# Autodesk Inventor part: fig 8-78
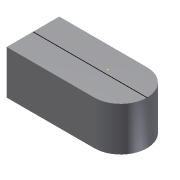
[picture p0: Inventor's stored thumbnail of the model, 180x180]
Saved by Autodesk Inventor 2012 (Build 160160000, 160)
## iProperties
Created: 2011-07
Part Number: fig 8-78
Material: Default
Document SubType Name: Modeling
Designer: CadCim
Density: 1 g/cm^3
Author: CadCim
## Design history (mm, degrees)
sketch "Sketch1"
  geometry: L1 (-16, 5)-(-16, -7); L2 (-16, -7)-(4, -7); L3 (4, 5)-(-16, 5); A1 r 6 centre (4, -1) between (4, -7) and (4, 5); 1 further point
  constraints: 6 end point, 2 point on circle, 2 tangent, 1 centre point, 1 parallel, 1 perpendicular, 1 vertical
extrude "Extrusion1" new body sketch "Sketch1" distance "d0" = 10; taper "d1" = 0 deg
sketch "Sketch2"
  geometry: L1 (-16, -1)-(10, -1); 1 further point
  constraints: 2 end point, 1 horizontal
body "Solid1"
